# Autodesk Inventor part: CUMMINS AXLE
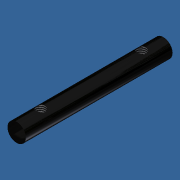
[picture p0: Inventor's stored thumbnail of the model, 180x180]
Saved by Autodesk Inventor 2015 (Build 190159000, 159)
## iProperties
Created: 2014-10
Part Number: CUMMINS AXLE
Material: Generic
Document SubType Name: Modeling
Designer: caovt
Density: 1 g/cm^3
Appearance: Default
Author: caovt
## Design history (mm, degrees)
sketch "Sketch1"
  geometry: C1 r 6.35 at (0, 0); 1 further point
  constraints: 1 centre point, 1 coincident
  dimensions: "d0" = 12.7 diameter of C1
extrude "Extrusion1" new body sketch "Sketch1" distance "d1" = 101.6; taper "d2" = 0 deg
workplane "Work Plane1"
  workaxis "Work Axis1"
sketch "Sketch2"
  geometry: L1 (0, -6.35)-(0, 6.35) reference; L2 (-101.6, 6.35)-(-101.6, -6.35) reference; L3 (-101.6, 6.35)-(0, 6.35) reference; L4 (-101.6, -6.35)-(0, -6.35) reference; L5 (0, -6.35)-(0, 6.35) reference; C1 r 3.175 at (-86.482, 0); C2 r 3.175 at (-16.632, 0); 1 further point
  constraints: 2 centre point, 1 equal radius
  dimensions: "d4" = 6.35 diameter of C1; "d5" = 69.85 distance of C1.centre C2.centre
extrude "Extrusion2" cut sketch "Sketch2" stored distance "d6" = 101.6; taper "d7" = 0 deg
thread "Thread1" dims "d8" = 25.4, "d9" = 0
thread "Thread2" dims "d10" = 25.4, "d11" = 0
workaxis "Work Axis2"
workaxis "Work Axis3"
workaxis "Work Axis4"
workplane "Work Plane2"
workplane "Work Plane3"
body "Solid1"
node "Projected Loop1"
other parameters: "d3" = 0
